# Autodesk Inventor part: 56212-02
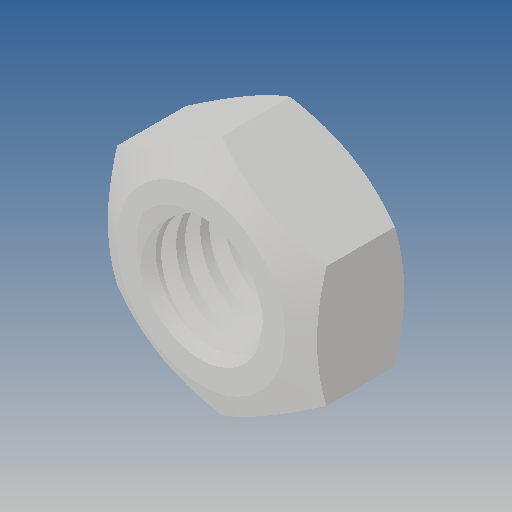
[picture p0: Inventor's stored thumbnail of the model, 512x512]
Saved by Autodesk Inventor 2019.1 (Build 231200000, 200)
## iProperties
Created: 2012-09
Part Number: 56212-02
Material: Ogólny
Document SubType Name: Modeling
Designer: CADENGINEERING4
Density: 1 g/cm^3
Appearance: Domyślna
Author: CADENGINEERING4
Revision Number: ÈÎºÎ
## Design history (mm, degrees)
feature "¾µÏò1"
node "Bryła1"
